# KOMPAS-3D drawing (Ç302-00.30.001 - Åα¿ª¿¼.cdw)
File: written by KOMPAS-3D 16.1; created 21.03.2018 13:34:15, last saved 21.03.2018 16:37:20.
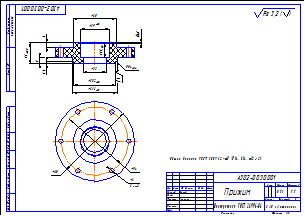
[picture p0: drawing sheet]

Sheet 1: A3, landscape

Title block, sheet 1: name: Прижим; designation: А302-00.30.001; material: Полипропилен  ГОСТ 26996-86; mass: 0,13; scale: 1:1; sheets: 1; organisation: ЗАО «Астерион»; sheet format: A3; stored path: Z:\Мембранные насосы\Мембранный электропривод\А302-00.00.000 - ASTRA-302 (МЭ200)\Чертежи\А302-00.30.001 - Прижим.cdw; drawn by: Милов; technical control: Лучихин

Views: Вид 1, Местный разрез 1, Вид:1, Проекционный вид 2
Referenced files in Z:\Мембранные насосы\Мембранный электропривод\А302-00.00.000 - ASTRA-302 (МЭ200)\3Д\: А302-00.30.001 - Прижим.m3d
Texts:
  Общие допуски ГОСТ 30893.2-mK (H14, h14,  t2/2).
  Ra 3,2
  Ra 3,2 ( )
Dimensions and other numbers on the sheet: 32; 39; 1; 20,5; 60; 58,2; 61,6; 0,4; 6; 3,6; 9; 29; 1,6; 110; 94; 6 отв.; 1:1; 0,13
